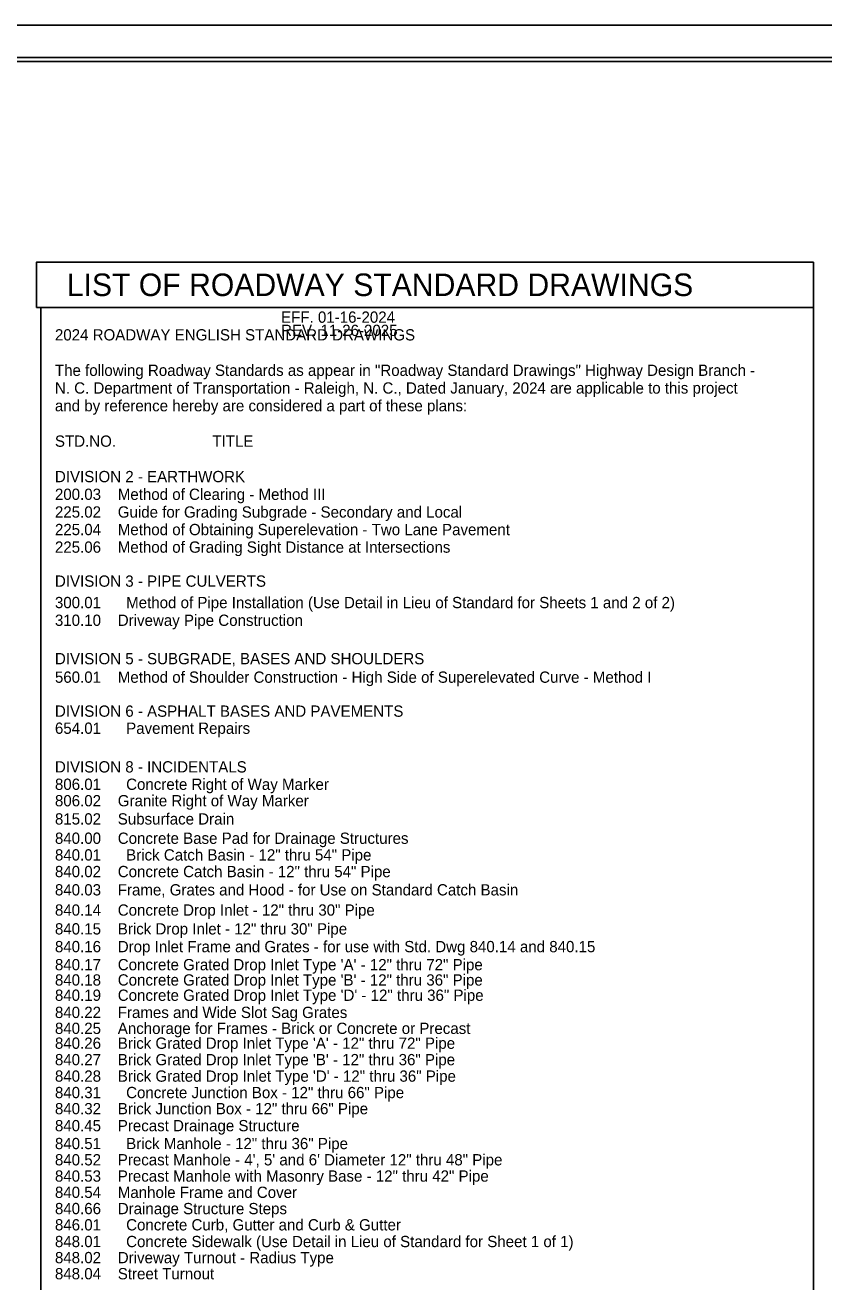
# Model space of a CAD drawing. Extents: x 5863093 to 5864777, y 1244886 to 1246112.
# Drawn here: x 5863774 to 5864270, y 1245331 to 1246112 of the extents above; entities that cross this region are included whole.
import ezdxf

# ---------------------------------------------------------------- set-up
doc = ezdxf.new("R2010")
doc.units = 0
for name, color, linetype in [('Default', 7, 'Continuous'), ('Old_Level_1', 7, 'Continuous'), ('Old_Level_40', 7, 'Continuous'), ('Sheet Cutting Line CELL', 7, 'Continuous'), ('Sheet Plan CELL', 7, 'Continuous'), ('Sheet Plot Border Inside CELL', 7, 'Continuous'), ('Sheet Plot Border Outside CELL', 7, 'Continuous')]:
    doc.layers.add(name, color=color, linetype=linetype)

msp = doc.modelspace()

# ---------------------------------------------------------------- linework, layer by layer
at = {"layer": 'Old_Level_1'}
msp.add_lwpolyline([(5863783.68, 1245217.59), (5864263.42, 1245217.59), (5864263.42, 1245936.31), (5863783.68, 1245936.31)], close=True, dxfattribs=at)
at = {"layer": 'Old_Level_40'}
msp.add_lwpolyline([(5863780.86, 1245936.31), (5864263.42, 1245936.31), (5864263.42, 1245964.31), (5863780.86, 1245964.31)], close=True, dxfattribs=at)
at = {"layer": 'Sheet Cutting Line CELL'}
msp.add_line((5864776.85, 1246111.53), (5863093.35, 1246111.53), dxfattribs=at)
at = {"layer": 'Sheet Plan CELL'}
for points in [[(5863259.83, 1245039.04), (5863259.81, 1246089.01), (5864559.8, 1246089.05), (5864559.81, 1245938.99), (5864759.85, 1245938.98), (5864759.85, 1245039.04)], [(5864759.87, 1246089.04), (5863259.83, 1246089.04), (5863259.83, 1245039.04), (5864759.85, 1245039.04)]]:
    msp.add_lwpolyline(points, close=True, dxfattribs=at)
at = {"layer": 'Sheet Plot Border Inside CELL'}
msp.add_lwpolyline([(5863106.35, 1245036.53), (5864772.33, 1245036.54), (5864772.35, 1246091.53), (5863106.35, 1246091.53)], close=True, dxfattribs=at)
at = {"layer": 'Sheet Plot Border Outside CELL'}
msp.add_lwpolyline([(5863093.35, 1245016.53), (5864776.85, 1245016.53), (5864776.85, 1246111.53), (5863093.35, 1246111.53)], close=True, dxfattribs=at)

# ---------------------------------------------------------------- texts
at = {"layer": 'Default'}
for s, p in [('840.00    Concrete Base Pad for Drainage Structures', (5863792.38, 1245603.19)), ('840.01      Brick Catch Basin - 12" thru 54" Pipe', (5863792.38, 1245592.84)), ('840.02    Concrete Catch Basin - 12" thru 54" Pipe', (5863792.38, 1245582.5)), ('840.17    Concrete Grated Drop Inlet Type \'A\' - 12" thru 72" Pipe', (5863792.38, 1245524.7)), ('840.18    Concrete Grated Drop Inlet Type \'B\' - 12" thru 36" Pipe', (5863792.38, 1245515.2)), ('840.19    Concrete Grated Drop Inlet Type \'D\' - 12" thru 36" Pipe', (5863792.38, 1245505.71)), ('840.22    Frames and Wide Slot Sag Grates', (5863792.38, 1245495.05)), ('840.25    Anchorage for Frames - Brick or Concrete or Precast', (5863792.38, 1245485.16)), ('840.26    Brick Grated Drop Inlet Type \'A\' - 12" thru 72" Pipe', (5863792.38, 1245475.93)), ('840.27    Brick Grated Drop Inlet Type \'B\' - 12" thru 36" Pipe', (5863792.38, 1245465.72)), ('840.28    Brick Grated Drop Inlet Type \'D\' - 12" thru 36" Pipe', (5863792.38, 1245455.5)), ('840.31      Concrete Junction Box - 12" thru 66" Pipe', (5863792.38, 1245445.29)), ('840.32    Brick Junction Box - 12" thru 66" Pipe', (5863792.38, 1245435.29)), ('840.51      Brick Manhole - 12" thru 36" Pipe', (5863792.38, 1245413.63)), ('840.52    Precast Manhole - 4\', 5\' and 6\' Diameter 12" thru 48" Pipe', (5863792.38, 1245403.54)), ('840.53    Precast Manhole with Masonry Base - 12" thru 42" Pipe', (5863792.38, 1245393.44)), ('840.54    Manhole Frame and Cover', (5863792.38, 1245383.35))]:
    msp.add_text(s, height=7, dxfattribs=at).set_placement(p)
at = {"layer": 'Old_Level_1'}
for s, p in [('                                                      EFF. 01-16-2024', (5863792.38, 1245926.74)), ('                                                      REV. 11-26-2025', (5863792.38, 1245918.52)), ('2024 ROADWAY ENGLISH STANDARD DRAWINGS', (5863792.38, 1245915.74)), ('The following Roadway Standards as appear in "Roadway Standard Drawings" Highway Design Branch -', (5863792.38, 1245893.74)), ('N. C. Department of Transportation - Raleigh, N. C., Dated January, 2024 are applicable to this project', (5863792.38, 1245882.74)), ('and by reference hereby are considered a part of these plans:', (5863792.38, 1245871.74)), ('STD.NO.                       TITLE', (5863792.38, 1245849.74)), ('DIVISION 2 - EARTHWORK', (5863792.38, 1245827.74)), ('200.03    Method of Clearing - Method III', (5863792.38, 1245816.74)), ('225.02    Guide for Grading Subgrade - Secondary and Local', (5863792.38, 1245805.74)), ('225.04    Method of Obtaining Superelevation - Two Lane Pavement', (5863792.38, 1245794.85)), ('225.06    Method of Grading Sight Distance at Intersections', (5863792.38, 1245783.95)), ('DIVISION 3 - PIPE CULVERTS', (5863792.38, 1245762.83)), ('300.01      Method of Pipe Installation (Use Detail in Lieu of Standard for Sheets 1 and 2 of 2)', (5863792.38, 1245749.52)), ('310.10    Driveway Pipe Construction ', (5863792.38, 1245738.52)), ('DIVISION 5 - SUBGRADE, BASES AND SHOULDERS', (5863792.38, 1245714.69)), ('560.01    Method of Shoulder Construction - High Side of Superelevated Curve - Method I', (5863792.38, 1245703.2)), ('DIVISION 6 - ASPHALT BASES AND PAVEMENTS', (5863792.38, 1245682.1)), ('654.01      Pavement Repairs', (5863792.38, 1245671.5)), ('DIVISION 8 - INCIDENTALS', (5863792.38, 1245647.5)), ('806.01      Concrete Right of Way Marker', (5863792.38, 1245636.7)), ('806.02    Granite Right of Way Marker', (5863792.38, 1245626.48)), ('815.02    Subsurface Drain', (5863792.38, 1245615.19)), ('840.03    Frame, Grates and Hood - for Use on Standard Catch Basin', (5863792.38, 1245571.15)), ('840.14    Concrete Drop Inlet - 12" thru 30" Pipe', (5863792.38, 1245558.6)), ('840.15    Brick Drop Inlet - 12" thru 30" Pipe', (5863792.38, 1245546.92)), ('840.16    Drop Inlet Frame and Grates - for use with Std. Dwg 840.14 and 840.15', (5863792.38, 1245535.9)), ('840.45    Precast Drainage Structure', (5863792.38, 1245424.74)), ('840.66    Drainage Structure Steps', (5863792.38, 1245373.25)), ('846.01      Concrete Curb, Gutter and Curb & Gutter', (5863792.38, 1245363.16)), ('848.01      Concrete Sidewalk (Use Detail in Lieu of Standard for Sheet 1 of 1)', (5863792.38, 1245352.79)), ('848.02    Driveway Turnout - Radius Type', (5863792.38, 1245342.8)), ('848.04    Street Turnout', (5863792.38, 1245332.8))]:
    msp.add_text(s, height=7, dxfattribs=at).set_placement(p)
at = {"layer": 'Old_Level_40'}
msp.add_text('LIST OF ROADWAY STANDARD DRAWINGS', height=14, dxfattribs=at).set_placement((5863799.75, 1245943.31))

doc.saveas('drawing.dxf')
